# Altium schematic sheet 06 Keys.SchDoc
size 264 x 185 mm
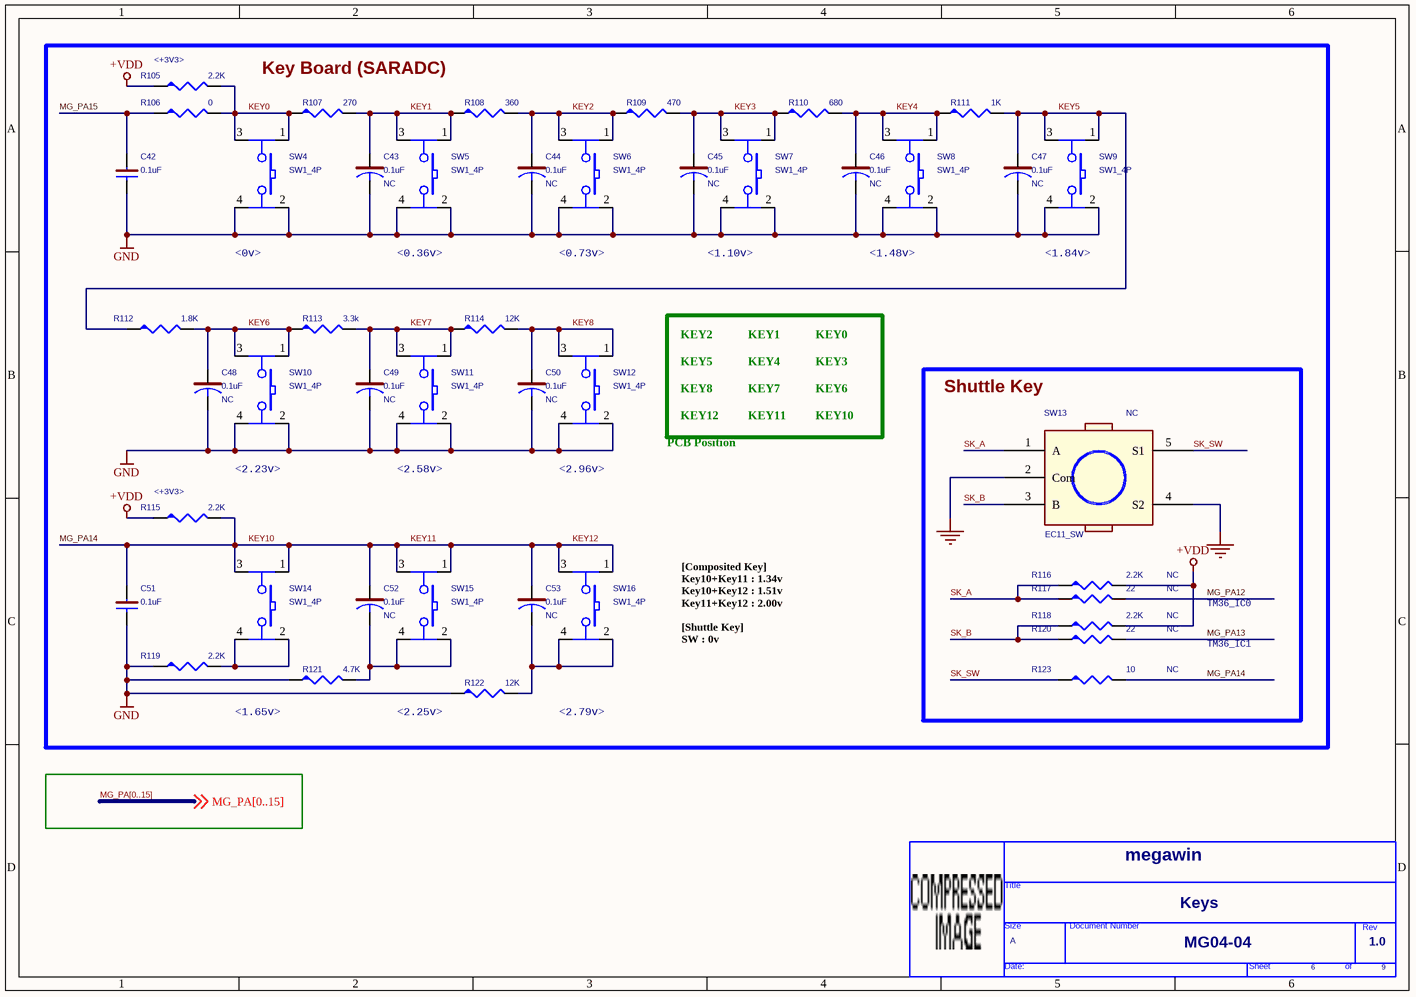
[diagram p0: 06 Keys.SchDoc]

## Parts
*  OrgName: megawin  Doc: MG04-04  RevCode: 1.0  Title: Keys  Page Size: A  Page Number: 6  Page Count: 9  (hidden comment: TitleBlock_MegaWin)  (graphical)
C42  0.1uF  [C-0603]
C43  0.1uF  Assembly: NC  [C-0805]
C44  0.1uF  Assembly: NC  [C-0805]
C45  0.1uF  Assembly: NC  [C-0805]
C46  0.1uF  Assembly: NC  [C-0805]
C47  0.1uF  Assembly: NC  [C-0805]
C48  0.1uF  Assembly: NC  [C-0805]
C49  0.1uF  Assembly: NC  [C-0805]
C50  0.1uF  Assembly: NC  [C-0805]
C51  0.1uF  [C-0603]
C52  0.1uF  Assembly: NC  [C-0805]
C53  0.1uF  Assembly: NC  [C-0805]
R105  2.2K  [R-0603]
R106  0  [R-0603]
R107  270  [R-0603]
R108  360  [R-0603]
R109  470  [R-0603]
R110  680  [R-0603]
R111  1K  [R-0603]
R112  1.8K  [R-0603]
R113  3.3k  [R-0603]
R114  12K  [R-0603]
R115  2.2K  [R-0603]
R116  2.2K  Assembly: NC  [R-0603]
R117  22  Assembly: NC  [R-0603]
R118  2.2K  Assembly: NC  [R-0603]
R119  2.2K  [R-0603]
R120  22  Assembly: NC  [R-0603]
R121  4.7K  [R-0603]
R122  12K  [R-0603]
R123  10  Assembly: NC  [R-0603]
SW4  SW1_4P  [SW-TACT-P4.5X6.5-Z6.2X6.2X5]
SW5  SW1_4P  [SW-TACT-P4.5X6.5-Z6.2X6.2X5]
SW6  SW1_4P  [SW-TACT-P4.5X6.5-Z6.2X6.2X5]
SW7  SW1_4P  [SW-TACT-P4.5X6.5-Z6.2X6.2X5]
SW8  SW1_4P  [SW-TACT-P4.5X6.5-Z6.2X6.2X5]
SW9  SW1_4P  [SW-TACT-P4.5X6.5-Z6.2X6.2X5]
SW10  SW1_4P  [SW-TACT-P4.5X6.5-Z6.2X6.2X5]
SW11  SW1_4P  [SW-TACT-P4.5X6.5-Z6.2X6.2X5]
SW12  SW1_4P  [SW-TACT-P4.5X6.5-Z6.2X6.2X5]
SW13  EC11_SW  Assembly: NC  [SW5P_EC11]
SW14  SW1_4P  [SW-TACT-P4.5X6.5-Z6.2X6.2X5]
SW15  SW1_4P  [SW-TACT-P4.5X6.5-Z6.2X6.2X5]
SW16  SW1_4P  [SW-TACT-P4.5X6.5-Z6.2X6.2X5]

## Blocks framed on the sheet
Key Board (SARADC): C42-C53 R105-R115 R119 R121 R122 SW4-SW12 SW14-SW16
Shuttle Key: R116-R118 R120 R123 SW13

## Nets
+VDD: R105.1 R115.1 R116.2 R118.2
GND: C42.2 C43.2 C44.2 C45.2 C46.2 C47.2 C48.2 C49.2 C50.2 C51.2 R119.1 R121.1 R122.1 SW4.2 SW4.4 SW5.2 SW5.4 SW6.2 SW6.4 SW7.2 SW7.4 SW8.2 SW8.4 SW9.2 SW9.4 SW10.2 SW10.4 SW11.2 SW11.4 SW12.2 SW12.4 SW13.2(Com) SW13.4(S2)
KEY0: R105.2 R106.2 R107.1 SW4.1 SW4.3
KEY1: C43.1 R107.2 R108.1 SW5.1 SW5.3
KEY2: C44.1 R108.2 R109.1 SW6.1 SW6.3
KEY3: C45.1 R109.2 R110.1 SW7.1 SW7.3
KEY4: C46.1 R110.2 R111.1 SW8.1 SW8.3
KEY5: C47.1 R111.2 R112.1 SW9.1 SW9.3
KEY6: C48.1 R112.2 R113.1 SW10.1 SW10.3
KEY7: C49.1 R113.2 R114.1 SW11.1 SW11.3
KEY8: C50.1 R114.2 SW12.1 SW12.3
KEY10: C51.1 C52.1 C53.1 R115.2 R123.2 SW14.1 SW14.3 SW15.1 SW15.3 SW16.1 SW16.3  [also labelled KEY11, KEY12, MG_PA14]
MG_PA12: R117.2
MG_PA13: R120.2
MG_PA15: C42.1 R106.1
SK_A: R116.1 R117.1 SW13.1(A)
SK_B: R118.1 R120.1 SW13.3(B)
SK_SW: R123.1 SW13.5(S1)
NetC52_2: C52.2 R121.2 SW15.2 SW15.4
NetC53_2: C53.2 R122.2 SW16.2 SW16.4
NetR119_2: R119.2 SW14.2 SW14.4

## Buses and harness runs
bus MG_PA[0..15]

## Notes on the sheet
- (near R105) <+3V3>
- (near SW4) <0v>
- (near SW5) <0.36v>
- (near SW6) <0.73v>
- (near SW7) <1.10v>
- (near SW8) <1.48v>
- (near SW9) <1.84v>
- KEY2
- KEY1
- KEY0
- KEY5
- KEY8
- KEY4
- KEY7
- KEY3
- KEY6
- <2.23v>
- (near SW11) <2.58v>
- (near SW12) <2.96v>
- PCB Position
- KEY12
- KEY11
- KEY10
- (near R115) <+3V3>
- TM36_IC0
- TM36_IC1
- <1.65v>
- (near R122) <2.25v>
- <2.79v>
- [Composited Key]
  Key10+Key11 : 1.34v
  Key10+Key12 : 1.51v
  Key11+Key12 : 2.00v
  [Shuttle Key]
  SW : 0v

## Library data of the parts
C42 C51 = CAP-NP: 2ND PART FIELD: SMD_0805
C43-C50 C52 C53 = CAP: 2ND PART FIELD: SMD_0805
R105 R115 = R: 2ND PART FIELD: SMD_0805
R106 R112 R116-R120 R123 = R
R107-R111 R113 R114 R121 R122 = R: 2ND PART FIELD: SMD_1
SW4 SW10 SW14 = SW-PB-4P: Function: Power KEY
SW5 SW11 SW15 = SW-PB-4P: Function: Return KEY
SW6 SW12 SW16 = SW-PB-4P: Function: + KEY
SW7 = SW-PB-4P: Function: Up KEY
SW8 = SW-PB-4P: Function: Down KEY
SW9 = SW-PB-4P: Function: - KEY
SW13 = SW-EC11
